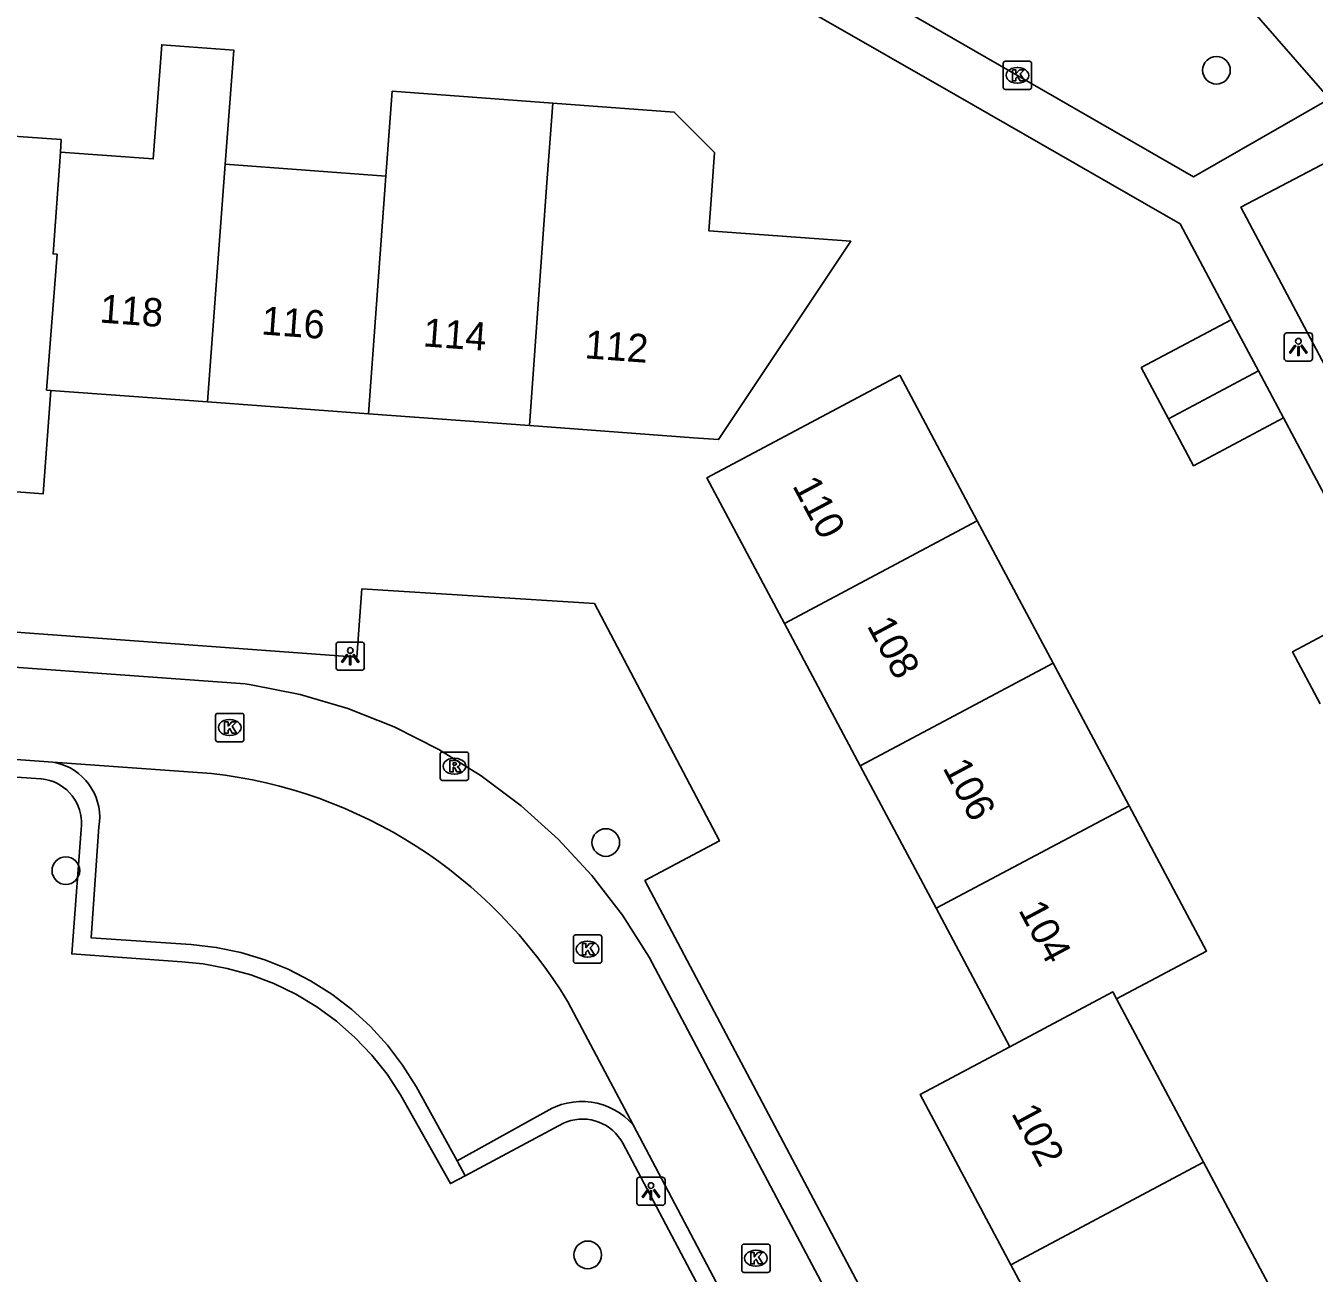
# Model space of a CAD drawing. Extents: x 160304 to 160954, y 383686 to 384161.
# Drawn here: x 160552.85 to 160598.37, y 383895.48 to 383939.55 of the extents above; entities that cross this region are included whole.
import ezdxf

# ---------------------------------------------------------------- set-up
doc = ezdxf.new("R2010")
doc.units = 0
for name, color, linetype in [('IMGEO_Boom', 7, 'Continuous'), ('IMGEO_Kolk', 7, 'Continuous'), ('IMGEO_Lichtpunt', 7, 'Continuous'), ('IMGEO_Muur', 7, 'Continuous'), ('IMGEO_Pand', 7, 'Continuous'), ('IMGEO_Pand_nummerreeks', 7, 'Continuous'), ('IMGEO_Rijbaan_lokaal_open', 7, 'Continuous'), ('IMGEO_Rioolput', 7, 'Continuous'), ('IMGEO_Voetpad_open', 7, 'Continuous')]:
    doc.layers.add(name, color=color, linetype=linetype)

msp = doc.modelspace()

# ---------------------------------------------------------------- linework, layer by layer
at = {"layer": 'IMGEO_Boom'}
for centre in [(160594.915, 383937.983), (160573.341, 383910.695), (160554.265, 383909.703), (160572.704, 383896.124)]:
    msp.add_circle(centre, 0.489, dxfattribs=at)
at = {"layer": 'IMGEO_Kolk'}
for p, q in [((160587.383, 383937.377), (160587.383, 383938.229)), ((160587.458, 383938.303), (160588.31, 383938.303)), ((160588.384, 383938.229), (160588.384, 383937.377)), ((160587.871, 383938.083), (160587.896, 383938.083)), ((160588.31, 383937.303), (160587.458, 383937.303)), ((160587.894, 383937.523), (160587.869, 383937.523)), ((160559.553, 383914.332), (160559.553, 383915.184)), ((160559.628, 383915.258), (160560.48, 383915.258)), ((160560.041, 383915.038), (160560.066, 383915.038)), ((160560.554, 383915.184), (160560.554, 383914.332)), ((160560.064, 383914.478), (160560.039, 383914.478)), ((160560.48, 383914.258), (160559.628, 383914.258)), ((160572.197, 383906.502), (160572.197, 383907.354)), ((160572.272, 383907.428), (160573.124, 383907.428)), ((160572.685, 383907.208), (160572.71, 383907.208)), ((160573.198, 383907.354), (160573.198, 383906.502)), ((160573.124, 383906.428), (160572.272, 383906.428)), ((160572.708, 383906.648), (160572.683, 383906.648)), ((160578.143, 383895.58), (160578.143, 383896.432)), ((160578.218, 383896.506), (160579.07, 383896.506)), ((160578.631, 383896.286), (160578.656, 383896.286)), ((160579.144, 383896.432), (160579.144, 383895.58)), ((160579.07, 383895.506), (160578.218, 383895.506)), ((160578.654, 383895.726), (160578.629, 383895.726))]:
    msp.add_line(p, q, dxfattribs=at)
for points in [[(160587.383, 383937.377), (160587.383, 383938.229)], [(160587.458, 383938.303), (160588.31, 383938.303)], [(160588.384, 383938.229), (160588.384, 383937.377)], [(160587.704, 383938.003), (160587.827, 383938.003), (160587.827, 383937.852), (160587.957, 383938.003), (160588.121, 383938.003), (160587.975, 383937.852), (160588.128, 383937.603), (160587.976, 383937.603), (160587.891, 383937.767), (160587.827, 383937.7), (160587.827, 383937.603), (160587.704, 383937.603), (160587.704, 383938.003)], [(160588.31, 383937.303), (160587.458, 383937.303)], [(160559.553, 383914.332), (160559.553, 383915.184)], [(160559.628, 383915.258), (160560.48, 383915.258)], [(160559.874, 383914.958), (160559.997, 383914.958), (160559.997, 383914.807), (160560.127, 383914.958), (160560.291, 383914.958), (160560.145, 383914.807), (160560.298, 383914.558), (160560.146, 383914.558), (160560.061, 383914.722), (160559.997, 383914.655), (160559.997, 383914.558), (160559.874, 383914.558), (160559.874, 383914.958)], [(160560.554, 383915.184), (160560.554, 383914.332)], [(160560.48, 383914.258), (160559.628, 383914.258)], [(160572.197, 383906.502), (160572.197, 383907.354)], [(160572.272, 383907.428), (160573.124, 383907.428)], [(160573.198, 383907.354), (160573.198, 383906.502)], [(160572.518, 383907.128), (160572.641, 383907.128), (160572.641, 383906.977), (160572.771, 383907.128), (160572.935, 383907.128), (160572.789, 383906.977), (160572.942, 383906.728), (160572.79, 383906.728), (160572.705, 383906.892), (160572.641, 383906.825), (160572.641, 383906.728), (160572.518, 383906.728), (160572.518, 383907.128)], [(160573.124, 383906.428), (160572.272, 383906.428)], [(160578.143, 383895.58), (160578.143, 383896.432)], [(160578.218, 383896.506), (160579.07, 383896.506)], [(160579.144, 383896.432), (160579.144, 383895.58)], [(160578.464, 383896.206), (160578.587, 383896.206), (160578.587, 383896.055), (160578.717, 383896.206), (160578.881, 383896.206), (160578.735, 383896.055), (160578.888, 383895.806), (160578.736, 383895.806), (160578.651, 383895.97), (160578.587, 383895.903), (160578.587, 383895.806), (160578.464, 383895.806), (160578.464, 383896.206)], [(160579.07, 383895.506), (160578.218, 383895.506)]]:
    msp.add_lwpolyline(points, dxfattribs=at)
for centre, start, end in [((160587.46, 383938.227), 91.552, 178.448), ((160587.46, 383938.227), 91.552, 178.448), ((160588.308, 383938.227), 1.552, 88.448), ((160588.308, 383938.227), 1.552, 88.448), ((160587.46, 383937.379), 181.552, 268.448), ((160587.46, 383937.379), 181.552, 268.448), ((160588.308, 383937.379), 271.552, 358.448), ((160588.308, 383937.379), 271.552, 358.448), ((160559.63, 383915.182), 91.552, 178.448), ((160559.63, 383915.182), 91.552, 178.448), ((160560.478, 383915.182), 1.552, 88.448), ((160560.478, 383915.182), 1.552, 88.448), ((160559.63, 383914.334), 181.552, 268.448), ((160559.63, 383914.334), 181.552, 268.448), ((160560.478, 383914.334), 271.552, 358.448), ((160560.478, 383914.334), 271.552, 358.448), ((160572.274, 383907.352), 91.552, 178.448), ((160572.274, 383907.352), 91.552, 178.448), ((160573.122, 383907.352), 1.552, 88.448), ((160573.122, 383907.352), 1.552, 88.448), ((160572.274, 383906.504), 181.552, 268.448), ((160572.274, 383906.504), 181.552, 268.448), ((160573.122, 383906.504), 271.552, 358.448), ((160573.122, 383906.504), 271.552, 358.448), ((160578.22, 383896.43), 91.552, 178.448), ((160578.22, 383896.43), 91.552, 178.448), ((160579.068, 383896.43), 1.552, 88.448), ((160579.068, 383896.43), 1.552, 88.448), ((160578.22, 383895.582), 181.552, 268.448), ((160578.22, 383895.582), 181.552, 268.448), ((160579.068, 383895.582), 271.552, 358.448), ((160579.068, 383895.582), 271.552, 358.448)]:
    msp.add_arc(centre, 0.0765, start, end, dxfattribs=at)
for centre, major_axis, ratio, start_param, end_param in [((160587.87, 383937.803), (-0.387, 0.002), 0.722429, 4.712389, 7.853982), ((160587.895, 383937.803), (-0.39, 0.002), 0.717154, 1.570796, 4.712389), ((160560.04, 383914.758), (-0.387, 0.002), 0.722429, 4.712389, 7.853982), ((160560.065, 383914.758), (-0.39, 0.002), 0.717154, 1.570796, 4.712389), ((160572.684, 383906.928), (-0.387, 0.002), 0.722429, 4.712389, 7.853982), ((160572.709, 383906.928), (-0.39, 0.002), 0.717154, 1.570796, 4.712389), ((160578.63, 383896.006), (-0.387, 0.002), 0.722429, 4.712389, 7.853982), ((160578.655, 383896.006), (-0.39, 0.002), 0.717154, 1.570796, 4.712389)]:
    msp.add_ellipse(centre, major_axis=major_axis, ratio=ratio, start_param=start_param, end_param=end_param, dxfattribs=at)
at = {"layer": 'IMGEO_Lichtpunt'}
for p, q in [((160597.311, 383928.609), (160597.311, 383927.802)), ((160597.311, 383928.609), (160597.311, 383927.802)), ((160598.213, 383928.704), (160597.405, 383928.704)), ((160598.213, 383928.704), (160597.405, 383928.704)), ((160598.307, 383927.802), (160598.307, 383928.609)), ((160598.307, 383927.802), (160598.307, 383928.609)), ((160597.405, 383927.708), (160598.213, 383927.708)), ((160597.405, 383927.708), (160598.213, 383927.708)), ((160563.814, 383917.684), (160563.814, 383916.877)), ((160563.814, 383917.684), (160563.814, 383916.877)), ((160564.716, 383917.779), (160563.908, 383917.779)), ((160564.716, 383917.779), (160563.908, 383917.779)), ((160564.81, 383916.877), (160564.81, 383917.684)), ((160564.81, 383916.877), (160564.81, 383917.684)), ((160563.908, 383916.783), (160564.716, 383916.783)), ((160563.908, 383916.783), (160564.716, 383916.783)), ((160574.438, 383898.776), (160574.438, 383897.969)), ((160574.438, 383898.776), (160574.438, 383897.969)), ((160575.34, 383898.871), (160574.532, 383898.871)), ((160575.34, 383898.871), (160574.532, 383898.871)), ((160575.434, 383897.969), (160575.434, 383898.776)), ((160575.434, 383897.969), (160575.434, 383898.776)), ((160574.532, 383897.875), (160575.34, 383897.875)), ((160574.532, 383897.875), (160575.34, 383897.875))]:
    msp.add_line(p, q, dxfattribs=at)
for points in [[(160597.685, 383928.273), (160597.724, 383928.245), (160597.536, 383927.983), (160597.498, 383928.01), (160597.685, 383928.273)], [(160597.787, 383928.225), (160597.834, 383928.225), (160597.834, 383927.903), (160597.787, 383927.903), (160597.787, 383928.225)], [(160597.897, 383928.245), (160597.935, 383928.272), (160598.122, 383928.01), (160598.083, 383927.982), (160597.897, 383928.245)], [(160564.188, 383917.348), (160564.227, 383917.32), (160564.039, 383917.058), (160564.001, 383917.085), (160564.188, 383917.348)], [(160564.29, 383917.3), (160564.337, 383917.3), (160564.337, 383916.978), (160564.29, 383916.978), (160564.29, 383917.3)], [(160564.4, 383917.32), (160564.438, 383917.347), (160564.625, 383917.085), (160564.586, 383917.057), (160564.4, 383917.32)], [(160574.812, 383898.44), (160574.851, 383898.412), (160574.663, 383898.15), (160574.625, 383898.177), (160574.812, 383898.44)], [(160574.914, 383898.392), (160574.961, 383898.392), (160574.961, 383898.07), (160574.914, 383898.07), (160574.914, 383898.392)], [(160575.024, 383898.412), (160575.062, 383898.439), (160575.249, 383898.177), (160575.21, 383898.149), (160575.024, 383898.412)]]:
    msp.add_lwpolyline(points, dxfattribs=at)
for centre in [(160597.81, 383928.407), (160564.313, 383917.482), (160574.937, 383898.574)]:
    msp.add_circle(centre, 0.0994, dxfattribs=at)
for centre, start, end in [((160597.405, 383928.609), 90, 180), ((160597.405, 383928.609), 90, 180), ((160598.213, 383928.609), 0, 90), ((160598.213, 383928.609), 0, 90), ((160597.405, 383927.802), 180, 270), ((160597.405, 383927.802), 180, 270), ((160598.213, 383927.802), 270, 0), ((160598.213, 383927.802), 270, 360), ((160563.908, 383917.684), 90, 180), ((160563.908, 383917.684), 90, 180), ((160564.716, 383917.684), 0, 90), ((160564.716, 383917.684), 0, 90), ((160563.908, 383916.877), 180, 270), ((160563.908, 383916.877), 180, 270), ((160564.716, 383916.877), 270, 0), ((160564.716, 383916.877), 270, 360), ((160574.532, 383898.776), 90, 180), ((160574.532, 383898.776), 90, 180), ((160575.34, 383898.776), 0, 90), ((160575.34, 383898.776), 0, 90), ((160574.532, 383897.969), 180, 270), ((160574.532, 383897.969), 180, 270), ((160575.34, 383897.969), 270, 0), ((160575.34, 383897.969), 270, 360)]:
    msp.add_arc(centre, 0.0946, start, end, dxfattribs=at)
at = {"layer": 'IMGEO_Muur'}
msp.add_lwpolyline([(160576.064, 383942.642), (160585.691, 383937.116)], dxfattribs=at)
at = {"layer": 'IMGEO_Pand'}
for points in [[(160554.076, 383935.092), (160557.355, 383934.851), (160557.652, 383938.884), (160560.196, 383938.696), (160559.899, 383934.663)], [(160565.575, 383934.246), (160565.795, 383937.238), (160571.469, 383936.82)], [(160571.469, 383936.82), (160575.758, 383936.504), (160577.186, 383935.075), (160577.063, 383933.4), (160576.983, 383932.311), (160581.996, 383931.943), (160577.328, 383924.933), (160576.444, 383924.998), (160570.641, 383925.425)], [(160570.641, 383925.425), (160571.25, 383933.85), (160571.469, 383936.82)], [(160554.076, 383935.092), (160554.094, 383935.53), (160551.058, 383935.753), (160548.576, 383935.935), (160548.279, 383931.897)], [(160553.736, 383926.669), (160553.587, 383926.68), (160553.958, 383931.479), (160553.811, 383931.49), (160554.076, 383935.092)], [(160559.899, 383934.663), (160559.265, 383926.262)], [(160559.899, 383934.663), (160565.575, 383934.246)], [(160564.957, 383925.843), (160565.575, 383934.246)], [(160593.221, 383925.666), (160592.258, 383927.475), (160595.436, 383929.167)], [(160595.436, 383929.167), (160596.399, 383927.359)], [(160579.651, 383918.439), (160576.913, 383923.58), (160583.724, 383927.208), (160586.463, 383922.067)], [(160596.399, 383927.359), (160593.221, 383925.666)], [(160596.399, 383927.359), (160597.283, 383925.699)], [(160547.64, 383923.448), (160553.467, 383923.019), (160553.736, 383926.669)], [(160559.265, 383926.262), (160553.736, 383926.669)], [(160564.957, 383925.843), (160559.265, 383926.262)], [(160570.641, 383925.425), (160564.957, 383925.843)], [(160597.283, 383925.699), (160594.105, 383924.007), (160593.221, 383925.666)], [(160586.463, 383922.067), (160579.651, 383918.439)], [(160586.463, 383922.067), (160589.145, 383917.032)], [(160598.584, 383915.595), (160597.607, 383917.431), (160600.784, 383919.123)], [(160582.333, 383913.405), (160579.651, 383918.439)], [(160582.333, 383913.405), (160589.145, 383917.032)], [(160589.145, 383917.032), (160591.827, 383911.997)], [(160585.015, 383908.37), (160582.333, 383913.405)], [(160591.827, 383911.997), (160585.015, 383908.37)], [(160591.827, 383911.997), (160594.565, 383906.858), (160591.388, 383905.166)], [(160587.621, 383903.478), (160585.015, 383908.37)], [(160591.388, 383905.166), (160591.255, 383905.416), (160587.621, 383903.478)], [(160591.388, 383905.166), (160594.458, 383899.403)], [(160587.646, 383895.777), (160584.445, 383901.786), (160587.621, 383903.478)], [(160587.646, 383895.777), (160594.458, 383899.403)], [(160594.458, 383899.403), (160597.603, 383893.497)], [(160590.792, 383889.87), (160587.646, 383895.777)]]:
    msp.add_lwpolyline(points, dxfattribs=at)
at = {"layer": 'IMGEO_Rijbaan_lokaal_open'}
for points in [[(160586.615, 383951.067), (160598.905, 383936.968)], [(160587.654, 383882.722), (160587.315, 383883.141), (160574.877, 383906.644), (160573.929, 383908.129), (160572.852, 383909.524), (160571.655, 383910.817), (160570.347, 383911.997), (160568.939, 383913.056), (160567.441, 383913.986), (160565.867, 383914.777), (160564.229, 383915.425), (160562.539, 383915.924), (160560.811, 383916.27), (160560.601, 383916.301), (160547.853, 383917.226)], [(160547.655, 383913.98), (160553.8, 383913.536)], [(160553.8, 383913.536), (160559.41, 383913.131)], [(160572.002, 383905.066), (160574.304, 383900.715)], [(160574.304, 383900.715), (160577.703, 383894.291)]]:
    msp.add_lwpolyline(points, dxfattribs=at)
msp.add_arc((160557.519, 383896.316), 16.922, 31.1394, 83.5826, dxfattribs=at)
at = {"layer": 'IMGEO_Rioolput'}
for p, q in [((160567.493, 383912.966), (160567.493, 383913.818)), ((160567.568, 383913.892), (160568.42, 383913.892)), ((160567.981, 383913.672), (160568.006, 383913.672)), ((160568.494, 383913.818), (160568.494, 383912.966)), ((160568.004, 383913.112), (160567.979, 383913.112)), ((160568.42, 383912.892), (160567.568, 383912.892))]:
    msp.add_line(p, q, dxfattribs=at)
for points in [[(160567.493, 383912.966), (160567.493, 383913.818)], [(160567.568, 383913.892), (160568.42, 383913.892)], [(160568.082, 383913.59), (160567.83, 383913.592), (160567.83, 383913.192)], [(160568.494, 383913.818), (160568.494, 383912.966)], [(160567.83, 383913.192), (160567.954, 383913.192), (160567.954, 383913.354), (160567.965, 383913.354)], [(160568.008, 383913.511), (160567.954, 383913.511), (160567.954, 383913.43)], [(160567.954, 383913.43), (160568.006, 383913.43)], [(160568.012, 383913.325), (160568.083, 383913.192), (160568.223, 383913.192), (160568.158, 383913.318)], [(160568.42, 383912.892), (160567.568, 383912.892)]]:
    msp.add_lwpolyline(points, dxfattribs=at)
for centre, radius, start, end in [((160567.57, 383913.816), 0.0765, 91.552, 178.448), ((160567.57, 383913.816), 0.0765, 91.552, 178.448), ((160568.081, 383913.48), 0.109, 350.3612, 89.416), ((160568.418, 383913.816), 0.0765, 1.552, 88.448), ((160568.418, 383913.816), 0.0765, 1.552, 88.448), ((160567.964, 383913.301), 0.0533, 26.0293, 88.6989), ((160567.99, 383913.619), 0.19, 274.7715, 282.9687), ((160568.014, 383913.415), 0.0964, 77.0061, 93.1865), ((160568.028, 383913.472), 0.0378, 276.6634, 79.6772), ((160568.079, 383913.48), 0.112, 277.5842, 350.9817), ((160568.063, 383913.265), 0.108, 29.5134, 73.7905), ((160567.57, 383912.968), 0.0765, 181.552, 268.448), ((160567.57, 383912.968), 0.0765, 181.552, 268.448), ((160568.418, 383912.968), 0.0765, 271.552, 358.448), ((160568.418, 383912.968), 0.0765, 271.552, 358.448)]:
    msp.add_arc(centre, radius, start, end, dxfattribs=at)
for centre, major_axis, ratio, start_param, end_param in [((160567.98, 383913.392), (-0.387, 0.002), 0.722429, 4.712389, 7.853982), ((160568.005, 383913.392), (-0.39, 0.002), 0.717154, 1.570796, 4.712389)]:
    msp.add_ellipse(centre, major_axis=major_axis, ratio=ratio, start_param=start_param, end_param=end_param, dxfattribs=at)
at = {"layer": 'IMGEO_Voetpad_open'}
for points in [[(160598.905, 383936.968), (160594.104, 383934.222), (160577.898, 383943.554)], [(160595.436, 383929.167), (160593.629, 383932.56), (160585.691, 383937.116), (160576.064, 383942.642)], [(160615.274, 383923.582), (160617.438, 383919.538), (160609.995, 383915.634), (160607.954, 383919.533), (160604.08, 383917.492), (160595.778, 383933.15), (160599.094, 383934.887), (160599.169, 383934.919), (160599.241, 383934.957), (160599.309, 383935.001), (160599.373, 383935.052), (160599.432, 383935.108), (160599.485, 383935.169), (160599.534, 383935.234), (160599.576, 383935.304), (160599.611, 383935.377), (160599.64, 383935.453), (160599.663, 383935.531), (160599.677, 383935.606)], [(160600.784, 383919.123), (160597.283, 383925.699)], [(160518.927, 383923.923), (160518.814, 383922.53), (160519.759, 383920.534), (160564.54, 383917.241), (160564.726, 383919.653), (160572.939, 383919.144), (160577.354, 383910.75), (160574.721, 383909.349), (160588.559, 383883.201)], [(160568.374, 383898.921), (160567.854, 383898.643), (160566.087, 383901.784), (160565.611, 383902.506), (160565.073, 383903.183), (160564.476, 383903.809), (160563.826, 383904.379), (160563.127, 383904.888), (160562.386, 383905.333), (160561.607, 383905.711), (160560.799, 383906.017), (160559.966, 383906.249), (160559.115, 383906.407), (160558.358, 383906.482), (160554.474, 383906.761), (160554.807, 383911.153), (160554.821, 383911.293), (160554.822, 383911.434), (160554.81, 383911.575), (160554.786, 383911.714), (160554.749, 383911.85), (160554.701, 383911.983), (160554.641, 383912.11), (160554.569, 383912.232), (160554.488, 383912.347), (160554.396, 383912.454), (160554.295, 383912.553), (160554.185, 383912.642), (160554.068, 383912.721), (160553.945, 383912.789), (160553.816, 383912.846), (160553.682, 383912.891), (160553.545, 383912.924), (160553.406, 383912.944), (160553.378, 383912.947), (160537.081, 383914.077)], [(160568.094, 383899.444), (160566.636, 383902.072), (160566.164, 383902.826), (160565.626, 383903.534), (160565.027, 383904.192), (160564.372, 383904.793), (160563.666, 383905.334), (160562.914, 383905.809), (160562.123, 383906.216), (160561.299, 383906.55), (160560.448, 383906.809), (160559.577, 383906.991), (160558.694, 383907.094), (160558.502, 383907.106), (160555.163, 383907.324), (160555.434, 383911.246), (160555.456, 383911.421), (160555.463, 383911.598), (160555.454, 383911.775), (160555.429, 383911.95), (160555.388, 383912.122), (160555.332, 383912.29), (160555.262, 383912.452), (160555.177, 383912.608), (160555.079, 383912.755), (160554.967, 383912.892), (160554.845, 383913.02), (160554.711, 383913.135), (160554.567, 383913.239), (160554.415, 383913.329), (160554.255, 383913.405), (160554.089, 383913.467), (160553.919, 383913.513), (160553.8, 383913.536)], [(160568.094, 383899.444), (160571.447, 383901.307), (160571.566, 383901.361), (160571.768, 383901.434), (160571.975, 383901.489), (160572.187, 383901.526), (160572.401, 383901.543), (160572.615, 383901.542), (160572.829, 383901.521), (160573.04, 383901.481), (160573.246, 383901.422), (160573.447, 383901.346), (160573.639, 383901.251), (160573.823, 383901.14), (160573.996, 383901.013), (160574.157, 383900.871), (160574.304, 383900.715)], [(160576.867, 383894.551), (160573.94, 383900.071), (160573.867, 383900.195), (160573.783, 383900.312), (160573.689, 383900.42), (160573.585, 383900.52), (160573.473, 383900.611), (160573.354, 383900.691), (160573.227, 383900.759), (160573.095, 383900.817), (160572.959, 383900.862), (160572.819, 383900.895), (160572.677, 383900.916), (160572.533, 383900.923), (160572.389, 383900.918), (160572.247, 383900.9), (160572.106, 383900.869), (160571.969, 383900.826), (160571.848, 383900.776), (160568.374, 383898.921)], [(160568.374, 383898.921), (160568.094, 383899.444)]]:
    msp.add_lwpolyline(points, dxfattribs=at)

# ---------------------------------------------------------------- texts
at = {"layer": 'IMGEO_Pand_nummerreeks'}
for s, rotation, p in [('118', 355.7914, (160555.439, 383929.071)), ('116', 355.7914, (160561.151, 383928.65)), ('114', 355.7914, (160566.865, 383928.23)), ('112', 355.7888, (160572.576, 383927.808)), ('110', 298.0435, (160579.915, 383923.306)), ('108', 298.0435, (160582.55, 383918.359)), ('106', 298.0435, (160585.225, 383913.338)), ('104', 298.0435, (160587.902, 383908.312)), ('102', 298.0418, (160587.65, 383901.13))]:
    msp.add_text(s, height=1, rotation=rotation, dxfattribs=at).set_placement(p)

doc.saveas('drawing.dxf')
